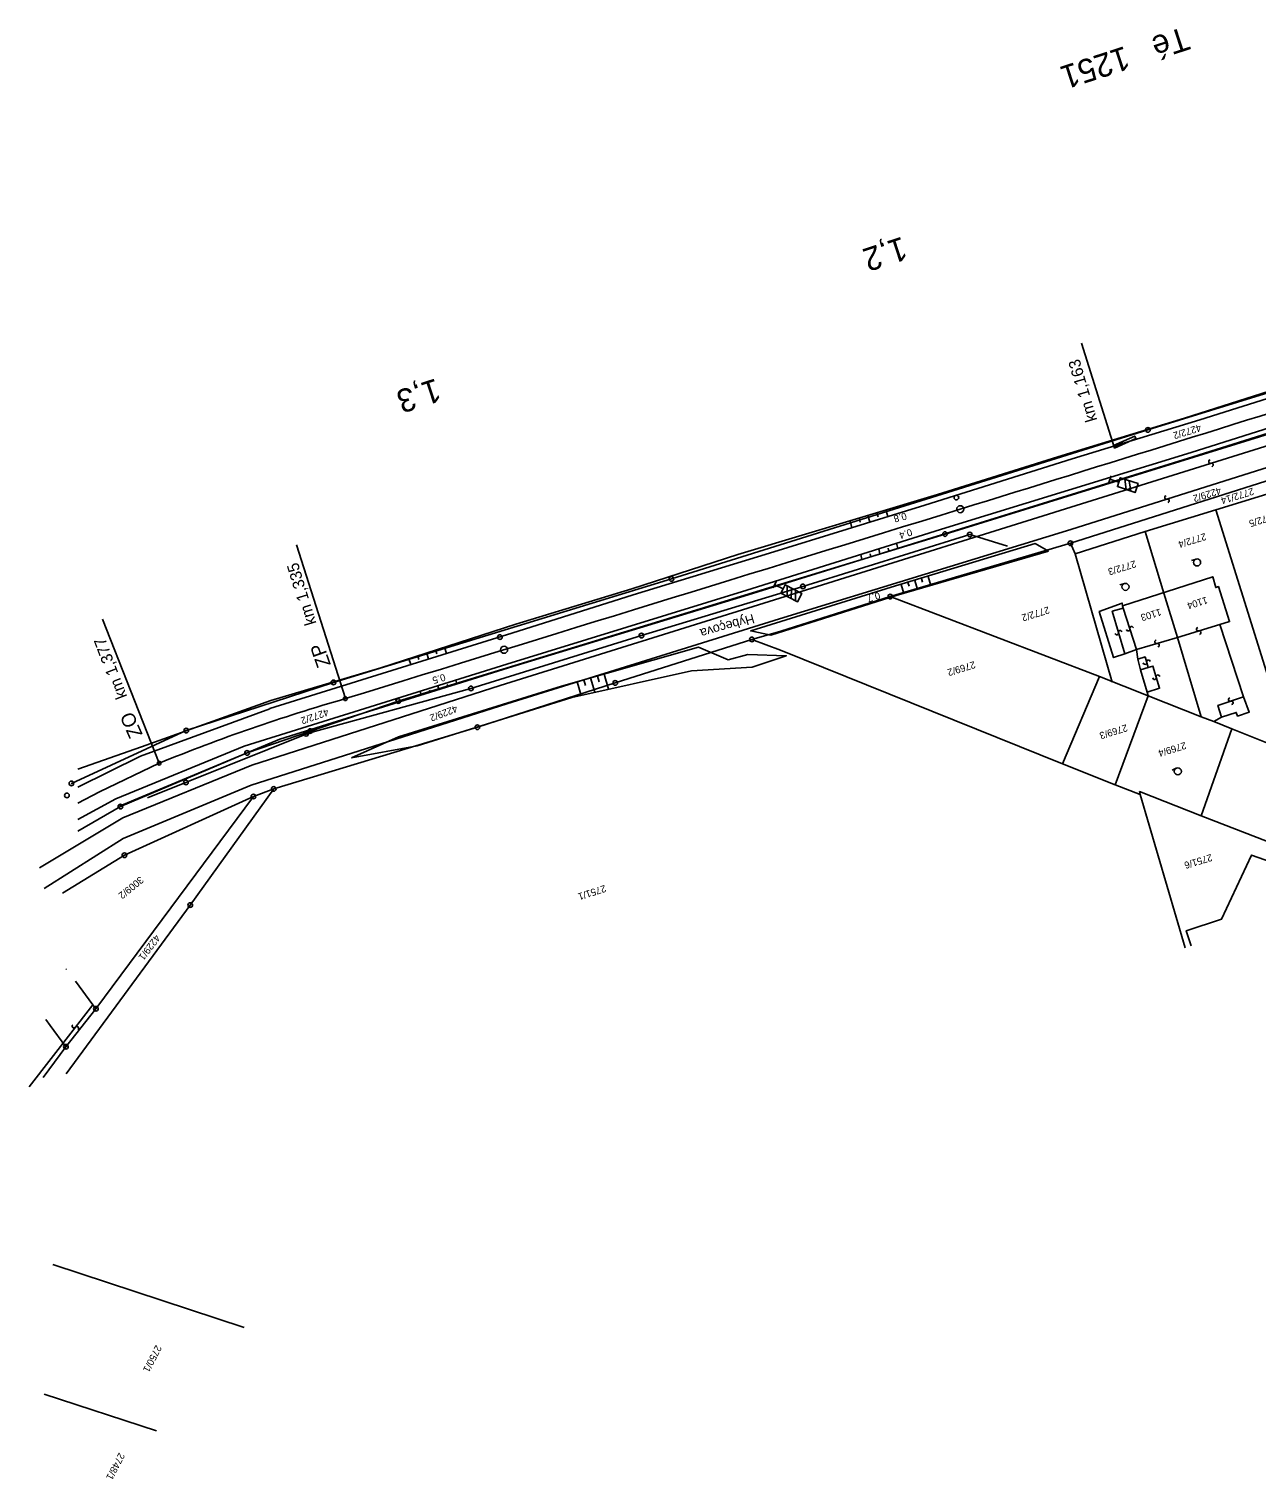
# Model space of a CAD drawing. Extents: x -658910 to -658078, y -1170373 to -1169331.
# Drawn here: x -658910.4 to -658648.2, y -1170242 to -1169932.4 of the extents above; entities that cross this region are included whole.
import ezdxf

# ---------------------------------------------------------------- set-up
doc = ezdxf.new("R2010")
doc.units = 0
for name, color, linetype in [('Vrstva 1', 7, 'Continuous'), ('Vrstva 10', 7, 'Continuous'), ('Vrstva 11', 7, 'Continuous'), ('Vrstva 14', 7, 'Continuous'), ('Vrstva 20', 7, 'Continuous'), ('Vrstva 26', 7, 'Continuous'), ('Vrstva 27', 7, 'Continuous'), ('Vrstva 38', 7, 'Continuous'), ('Vrstva 39', 7, 'Continuous'), ('Vrstva 6', 7, 'Continuous'), ('Vrstva 7', 7, 'Continuous'), ('Vrstva 8', 7, 'Continuous'), ('Vrstva 9', 7, 'Continuous')]:
    doc.layers.add(name, color=color, linetype=linetype)

msp = doc.modelspace()

# ---------------------------------------------------------------- linework, layer by layer
at = {"layer": 'Vrstva 1'}
for p, q in [((-658671.562, -1170017.973), (-658671.462, -1170017.973)), ((-658714.89, -1170040.211), (-658714.79, -1170040.211)), ((-658773.316, -1170049.791), (-658773.216, -1170049.791)), ((-658845.488, -1170071.906), (-658845.388, -1170071.906)), ((-658831.616, -1170075.877), (-658831.516, -1170075.877)), ((-658876.886, -1170082.189), (-658876.786, -1170082.189)), ((-658863.921, -1170086.955), (-658863.821, -1170086.955)), ((-658901.421, -1170093.457), (-658901.321, -1170093.457)), ((-658890.964, -1170098.41), (-658890.864, -1170098.41))]:
    msp.add_line(p, q, dxfattribs=at)
for points in [[(-658750.043, -1170042.514), (-658671.512, -1170017.973), (-658613.207, -1169999.979)], [(-658585.293, -1169999.957), (-658599.563, -1170004.705), (-658613.664, -1170008.939), (-658714.84, -1170040.211), (-658749.914, -1170050.912)], [(-658901.371, -1170093.457), (-658901.371, -1170093.457), (-658876.836, -1170082.189), (-658845.438, -1170071.906), (-658773.266, -1170049.791), (-658750.043, -1170042.514)], [(-658900.009, -1170103.697), (-658890.914, -1170098.41), (-658863.871, -1170086.955), (-658831.566, -1170075.877), (-658749.914, -1170050.912)]]:
    msp.add_lwpolyline(points, dxfattribs=at)
for centre in [(-658671.512, -1170017.973), (-658714.84, -1170040.211), (-658773.266, -1170049.791), (-658845.438, -1170071.906), (-658831.566, -1170075.877), (-658876.836, -1170082.189), (-658863.871, -1170086.955), (-658901.371, -1170093.457), (-658890.914, -1170098.41)]:
    msp.add_circle(centre, 0.499, dxfattribs=at)
at = {"layer": 'Vrstva 10'}
for p, q in [((-658735.117, -1170037.368), (-658734.704, -1170038.861)), ((-658733.201, -1170036.793), (-658732.958, -1170037.672)), ((-658731.286, -1170036.218), (-658730.881, -1170037.682)), ((-658729.37, -1170035.644), (-658729.127, -1170036.522)), ((-658727.455, -1170035.069), (-658727.058, -1170036.504)), ((-658728.759, -1170044.471), (-658728.984, -1170043.394)), ((-658726.849, -1170043.877), (-658726.984, -1170043.231)), ((-658724.939, -1170043.284), (-658725.166, -1170042.2)), ((-658732.579, -1170045.657), (-658732.803, -1170044.587)), ((-658730.669, -1170045.064), (-658730.804, -1170044.418)), ((-658825.509, -1170065.628), (-658825.088, -1170066.909)), ((-658823.607, -1170065.01), (-658823.354, -1170065.779)), ((-658821.704, -1170064.393), (-658821.269, -1170065.719)), ((-658829.314, -1170066.862), (-658828.907, -1170068.099)), ((-658827.412, -1170066.245), (-658827.159, -1170067.013)), ((-658819.071, -1170072.253), (-658819.277, -1170071.413)), ((-658826.709, -1170074.635), (-658826.913, -1170073.8)), ((-658824.799, -1170074.039), (-658824.922, -1170073.537)), ((-658822.89, -1170073.444), (-658823.095, -1170072.607)), ((-658820.981, -1170072.849), (-658821.104, -1170072.346))]:
    msp.add_line(p, q, dxfattribs=at)
for points in [[(-658858.81, -1170075.77), (-658835.33, -1170068.814), (-658806.5, -1170059.46), (-658781.728, -1170051.951), (-658759.08, -1170044.56), (-658716.43, -1170031.76), (-658690.72, -1170023.742), (-658663.72, -1170015.47), (-658630.927, -1170005.047), (-658619.527, -1170001.735), (-658614.09, -1169999.864), (-658613.911, -1169996.427), (-658615.839, -1169976.036), (-658616.28, -1169953.162), (-658614.25, -1169933.651)], [(-658610.105, -1169934.508), (-658612.959, -1169952.166), (-658613.171, -1169975.75), (-658611.485, -1169997.195), (-658611.739, -1169999.997), (-658613.983, -1170001.632), (-658619.297, -1170002.886), (-658632.661, -1170007.108), (-658660.45, -1170015.82), (-658687.716, -1170024.188), (-658719.16, -1170034.07), (-658752.32, -1170044.29), (-658781.421, -1170053.208), (-658807.34, -1170061.38), (-658834.998, -1170069.996)], [(-658623.66, -1170011.73), (-658661.96, -1170023.72), (-658756.86, -1170053.2), (-658808.03, -1170068.81), (-658856.9, -1170084.05), (-658891.09, -1170098.33)], [(-658714.67, -1170038.92), (-658662.28, -1170022.82), (-658628.54, -1170012.15)], [(-658900, -1170101.182), (-658891.86, -1170096.79), (-658864.47, -1170085.54), (-658808.39, -1170068.01), (-658757.16, -1170052.2), (-658714.67, -1170038.92)], [(-658721.308, -1170050.141), (-658720.723, -1170052.062)], [(-658719.873, -1170049.704), (-658719.637, -1170050.48)], [(-658718.438, -1170049.267), (-658717.841, -1170051.227)], [(-658724.178, -1170051.016), (-658723.604, -1170052.896)], [(-658722.743, -1170050.579), (-658722.511, -1170051.338)], [(-658834.998, -1170069.996), (-658859.033, -1170077.493)], [(-658793.385, -1170071.78), (-658792.557, -1170074.672)], [(-658791.942, -1170071.368), (-658791.602, -1170072.559)], [(-658790.5, -1170070.955), (-658789.624, -1170074.018)], [(-658789.058, -1170070.542), (-658788.698, -1170071.802)], [(-658787.616, -1170070.13), (-658786.691, -1170073.365)], [(-658858.81, -1170075.77), (-658886.37, -1170085.64), (-658900, -1170090.433)], [(-658900, -1170094.262), (-658886.64, -1170087.67), (-658858.98, -1170077.52)]]:
    msp.add_lwpolyline(points, dxfattribs=at)
for points in [[(-658692.759, -1170043.892), (-658695.624, -1170042.243), (-658726.306, -1170051.594), (-658756.332, -1170060.903), (-658752.062, -1170061.801), (-658725.258, -1170053.308)], [(-658841.563, -1170088.023), (-658831.521, -1170083.504), (-658796.721, -1170072.734), (-658767.485, -1170064.372), (-658761.109, -1170067.059), (-658756.94, -1170065.949), (-658748.723, -1170066.215), (-658755.985, -1170068.673), (-658768.941, -1170069.411), (-658794.544, -1170075.114), (-658827.528, -1170085.418)]]:
    msp.add_lwpolyline(points, close=True, dxfattribs=at)
at = {"layer": 'Vrstva 14'}
for centre in [(-658712.42, -1170032.43), (-658809.87, -1170062.23), (-658902.32, -1170096.04)]:
    msp.add_circle(centre, 0.5, dxfattribs=at)
at = {"layer": 'Vrstva 20'}
for p, q in [((-658679.383, -1170027.798), (-658679.857, -1170029.222)), ((-658676.458, -1170028.51), (-658676.141, -1170030.724)), ((-658675.193, -1170031.04), (-658675.509, -1170028.826)), ((-658750.867, -1170050.362), (-658751.553, -1170051.698)), ((-658748.529, -1170051.283), (-658748.554, -1170053.518)), ((-658747.664, -1170053.976), (-658747.639, -1170051.74)), ((-658746.751, -1170052.196), (-658746.774, -1170054.433))]:
    msp.add_line(p, q, dxfattribs=at)
for points in [[(-658679.62, -1170028.51), (-658677.723, -1170029.142), (-658678.039, -1170030.091), (-658674.244, -1170031.356), (-658673.612, -1170029.459), (-658677.406, -1170028.194), (-658677.723, -1170029.142)], [(-658751.21, -1170051.03), (-658749.431, -1170051.943), (-658749.888, -1170052.833), (-658746.33, -1170054.661), (-658745.416, -1170052.882), (-658748.974, -1170051.055), (-658749.431, -1170051.943)]]:
    msp.add_lwpolyline(points, dxfattribs=at)
at = {"layer": 'Vrstva 26'}
for p, q in [((-658678.468, -1170021.115), (-658678.706, -1170021.723)), ((-658677.982, -1170020.903), (-658678.291, -1170021.693)), ((-658677.496, -1170020.69), (-658677.805, -1170021.48)), ((-658677.038, -1170020.546), (-658677.32, -1170021.267)), ((-658676.818, -1170021.048), (-658677.059, -1170020.498)), ((-658676.824, -1170021.032), (-658676.833, -1170021.055)), ((-658676.818, -1170021.048), (-658676.818, -1170021.048))]:
    msp.add_line(p, q, dxfattribs=at)
for points in [[(-658674.069, -1170019.845), (-658678.65, -1170021.849), (-658678.891, -1170021.3), (-658674.311, -1170019.295), (-658674.069, -1170019.845)], [(-658701.47, -1170042.819), (-658709.55, -1170040.34), (-658745.18, -1170051.4)], [(-658745.18, -1170051.4), (-658779.65, -1170061.91), (-658816.05, -1170073.17)], [(-658816.05, -1170073.17), (-658850.74, -1170082.75), (-658885.09, -1170096.558)]]:
    msp.add_lwpolyline(points, dxfattribs=at)
msp.add_lwpolyline([(-658678.891, -1170021.3), (-658677.059, -1170020.498), (-658676.818, -1170021.048), (-658678.65, -1170021.849)], close=True, dxfattribs=at)
for centre in [(-658709.55, -1170040.34), (-658745.18, -1170051.4), (-658779.65, -1170061.91), (-658816.05, -1170073.17), (-658851.245, -1170082.857), (-658850.421, -1170082.287), (-658876.91, -1170093.27)]:
    msp.add_circle(centre, 0.5, dxfattribs=at)
at = {"layer": 'Vrstva 27'}
msp.add_line((-658678.65, -1170021.849), (-658685.668, -1169999.45), dxfattribs=at)
at = {"layer": 'Vrstva 38'}
for points in [[(-658853.304, -1170042.51), (-658842.88, -1170075.37)], [(-658894.763, -1170058.415), (-658882.62, -1170089.14)]]:
    msp.add_lwpolyline(points, dxfattribs=at)
for centre in [(-658842.88, -1170075.37), (-658882.62, -1170089.14)]:
    msp.add_circle(centre, 0.4, dxfattribs=at)
at = {"layer": 'Vrstva 6'}
msp.add_lwpolyline([(-658900, -1170097.715), (-658895.39, -1170095.24), (-658882.62, -1170089.14)], dxfattribs=at)
for centre in [(-658711.59, -1170034.91), (-658808.981, -1170064.933)]:
    msp.add_circle(centre, 0.75, dxfattribs=at)
for centre, radius, start, end in [((-665545.791, -1147911.264), 23155.173, 287.1664083, 287.4078056), ((-547459.91, -1531272.432), 377980.798, 107.11745833, 107.13828333), ((-658732.91, -1170456.97), 397.13, 106.07594, 112.14669)]:
    msp.add_arc(centre, radius, start, end, dxfattribs=at)
at = {"layer": 'Vrstva 8'}
for p, q in [((-658688.128, -1170042.182), (-658688.028, -1170042.182)), ((-658688.128, -1170042.182), (-658688.028, -1170042.182)), ((-658726.577, -1170053.572), (-658726.477, -1170053.572)), ((-658726.577, -1170053.572), (-658726.477, -1170053.572)), ((-658756.113, -1170062.727), (-658756.013, -1170062.727)), ((-658756.113, -1170062.727), (-658756.013, -1170062.727)), ((-658785.304, -1170072.021), (-658785.204, -1170072.021)), ((-658814.745, -1170081.465), (-658814.645, -1170081.465)), ((-658862.542, -1170096.26), (-658862.442, -1170096.26)), ((-658862.542, -1170096.26), (-658862.442, -1170096.26)), ((-658858.23, -1170094.633), (-658858.13, -1170094.633)), ((-658858.23, -1170094.633), (-658858.13, -1170094.633)), ((-658890.089, -1170108.813), (-658889.989, -1170108.813)), ((-658876.038, -1170119.434), (-658875.938, -1170119.434)), ((-658896.195, -1170141.572), (-658896.095, -1170141.572)), ((-658896.195, -1170141.572), (-658896.095, -1170141.572)), ((-658902.581, -1170149.688), (-658902.481, -1170149.688)), ((-658902.581, -1170149.688), (-658902.481, -1170149.688))]:
    msp.add_line(p, q, dxfattribs=at)
for points in [[(-658750.074, -1170053.912), (-658680.031, -1170031.988), (-658636.086, -1170018.248), (-658589.152, -1170004.176), (-658575.438, -1170000.053)], [(-658750.188, -1170058.359), (-658687.98, -1170039.244), (-658646.949, -1170026.285), (-658597.125, -1170011.18), (-658596.484, -1170013.23), (-658607.781, -1170016.664), (-658688.078, -1170042.182), (-658726.527, -1170053.572), (-658749.891, -1170060.961)], [(-658640.809, -1170086.922), (-658656.988, -1170035.021), (-658641.512, -1170030.291), (-658637.563, -1170043.293), (-658635.52, -1170050.398), (-658634.996, -1170051.859), (-658633.07, -1170058.375), (-658626.898, -1170077.652), (-658633.539, -1170089.834)], [(-658656.988, -1170035.021), (-658672.113, -1170039.701)], [(-658687.063, -1170044.438), (-658672.113, -1170039.701), (-658668.121, -1170052.848), (-658665.195, -1170062.299), (-658660.113, -1170079.238)], [(-658679.133, -1170071.836), (-658687.063, -1170044.438), (-658688.078, -1170042.182)], [(-658651.086, -1170074.998), (-658656.168, -1170059.514), (-658654.09, -1170058.92), (-658656.449, -1170051.438), (-658657.016, -1170051.652), (-658657.68, -1170049.348), (-658676.922, -1170055.516), (-658676.77, -1170056.045), (-658673.926, -1170064.844), (-658673.699, -1170066.908), (-658672.105, -1170066.453), (-658671.457, -1170068.709), (-658670.441, -1170068.42), (-658669.027, -1170073.158), (-658671.672, -1170073.965), (-658673.094, -1170069.205), (-658671.457, -1170068.709)], [(-658908.199, -1170111.508), (-658890.367, -1170100.813), (-658862.824, -1170089.561), (-658809.809, -1170072.594), (-658750.074, -1170053.912)], [(-658681.879, -1170070.646), (-658726.527, -1170053.572)], [(-658656.168, -1170059.514), (-658665.195, -1170062.299), (-658673.926, -1170064.844), (-658676.469, -1170065.828), (-658678.855, -1170066.613), (-658681.895, -1170056.779), (-658676.98, -1170054.961), (-658676.922, -1170055.516)], [(-658676.77, -1170056.045), (-658679.141, -1170056.721), (-658676.469, -1170065.828)], [(-658750.188, -1170058.359), (-658808.418, -1170076.5), (-658844.629, -1170088.006), (-658862.988, -1170093.809), (-658890.281, -1170105.262), (-658907.157, -1170115.934)], [(-658749.891, -1170060.961), (-658756.063, -1170062.727)], [(-658902.517, -1170155.47), (-658875.988, -1170119.434), (-658858.18, -1170094.633), (-658814.695, -1170081.465), (-658785.254, -1170072.021), (-658756.063, -1170062.727), (-658749.953, -1170065.01)], [(-658749.953, -1170065.01), (-658689.758, -1170089.258), (-658678.52, -1170093.789), (-658673.168, -1170095.848), (-658663.594, -1170128.594)], [(-658673.094, -1170069.205), (-658673.699, -1170066.908)], [(-658689.758, -1170089.258), (-658681.879, -1170070.646), (-658671.484, -1170074.795), (-658678.52, -1170093.789)], [(-658671.672, -1170073.965), (-658671.484, -1170074.795)], [(-658671.484, -1170074.795), (-658660.113, -1170079.238), (-658657.473, -1170080.25), (-658653.578, -1170081.787), (-658640.809, -1170086.922), (-658633.539, -1170089.834), (-658623.715, -1170093.627), (-658608.461, -1170099.402), (-658611.504, -1170107.906)], [(-658657.473, -1170080.25), (-658655.793, -1170079.355), (-658652.645, -1170078.301), (-658652.363, -1170079.104), (-658649.879, -1170078.289), (-658651.086, -1170074.998), (-658656.574, -1170076.824), (-658655.793, -1170079.355)], [(-658660.148, -1170100.391), (-658653.578, -1170081.787)], [(-658862.492, -1170096.26), (-658896.145, -1170141.572), (-658902.531, -1170149.688), (-658907.404, -1170156.249)], [(-658903.276, -1170116.909), (-658890.039, -1170108.813), (-658862.492, -1170096.26), (-658858.18, -1170094.633)], [(-658626.145, -1170113.541), (-658660.148, -1170100.391), (-658673.301, -1170095.209), (-658673.168, -1170095.848)], [(-658662.316, -1170128.127), (-658663.34, -1170124.938), (-658655.801, -1170122.422), (-658649.43, -1170108.76), (-658630.473, -1170115.4)], [(-658902.383, -1170133.092), (-658902.535, -1170133.202)], [(-658900.498, -1170135.681), (-658896.793, -1170140.77), (-658896.145, -1170141.572)], [(-658896.793, -1170140.77), (-658910.422, -1170158.293)], [(-658902.531, -1170149.688), (-658905.875, -1170145.17), (-658906.838, -1170143.909)], [(-658905.369, -1170196.205), (-658864.461, -1170209.621)], [(-658907.19, -1170223.865), (-658883.211, -1170231.717)]]:
    msp.add_lwpolyline(points, dxfattribs=at)
for centre in [(-658688.078, -1170042.182), (-658688.078, -1170042.182), (-658726.527, -1170053.572), (-658726.527, -1170053.572), (-658756.063, -1170062.727), (-658756.063, -1170062.727), (-658785.254, -1170072.021), (-658814.695, -1170081.465), (-658862.492, -1170096.26), (-658862.492, -1170096.26), (-658858.18, -1170094.633), (-658858.18, -1170094.633), (-658890.039, -1170108.813), (-658875.988, -1170119.434), (-658896.145, -1170141.572), (-658896.145, -1170141.572), (-658902.531, -1170149.688), (-658902.531, -1170149.688)]:
    msp.add_circle(centre, 0.499, dxfattribs=at)
for centre, radius, start, end in [((-658658.167, -1170024.756), 0.376, 100.39308, 286.70422), ((-658657.946, -1170025.476), 0.377, 279.71704, 107.38026), ((-658667.574, -1170032.403), 0.376, 100.55814, 286.86928), ((-658667.351, -1170033.123), 0.377, 279.8821, 107.54532), ((-658678.167, -1170061.374), 0.376, 189.38066, 15.6918), ((-658677.443, -1170061.166), 0.377, 8.70462, 196.36784), ((-658675.707, -1170060.554), 0.376, 190.941, 17.25213), ((-658674.989, -1170060.327), 0.377, 10.26496, 197.92817), ((-658660.786, -1170060.545), 0.376, 100.17663, 286.48776), ((-658660.568, -1170061.265), 0.377, 279.50059, 107.1638), ((-658669.664, -1170063.209), 0.376, 99.28171, 285.59284), ((-658669.457, -1170063.933), 0.377, 278.60566, 106.26888), ((-658672.143, -1170067.679), 0.376, 189.06743, 15.37856), ((-658671.418, -1170067.475), 0.377, 8.39139, 196.0546), ((-658670.095, -1170070.892), 0.376, 189.64721, 15.95834), ((-658669.373, -1170070.681), 0.377, 8.97116, 196.63438), ((-658653.942, -1170075.551), 0.376, 101.43472, 287.74585), ((-658653.709, -1170076.267), 0.377, 280.75868, 108.42189), ((-658900.831, -1170145.286), 0.376, 134.79213, 321.10327), ((-658900.243, -1170145.756), 0.377, 314.11609, 141.77931)]:
    msp.add_arc(centre, radius, start, end, dxfattribs=at)
at = {"layer": 'Vrstva 9'}
for p, q in [((-658661.234, -1170045.566), (-658662.19, -1170045.858)), ((-658676.523, -1170050.777), (-658677.479, -1170051.069)), ((-658665.453, -1170090.217), (-658666.354, -1170090.65))]:
    msp.add_line(p, q, dxfattribs=at)
for centre in [(-658661.014, -1170046.283), (-658676.303, -1170051.494), (-658665.127, -1170090.892)]:
    msp.add_circle(centre, 0.75, dxfattribs=at)

# ---------------------------------------------------------------- texts
at = {"layer": 'Vrstva 11'}
for s, rotation, p in [('4272/2', 197.15141, (-658660.403, -1170016.754)), ('0.8', 195.46354, (-658723.256, -1170035.605)), ('0.4', 197.72474, (-658722.131, -1170039.043)), ('0,7', 196.95334, (-658728.945, -1170052.565)), ('0.5', 196.49234, (-658821.761, -1170070.031)), ('4272/2', 198.92819, (-658846.735, -1170077.48))]:
    msp.add_text(s, height=1.5, rotation=rotation, dxfattribs=at).set_placement(p)
at = {"layer": 'Vrstva 27'}
msp.add_text('km 1,163', height=2.5, rotation=106.21318, dxfattribs=at).set_placement((-658682.326, -1170015.878))
at = {"layer": 'Vrstva 39'}
for s, height, rotation, p in [('km 1,335', 2.5, 106.94394, (-658849.029, -1170059.28)), ('km 1,377', 2.5, 110.86654, (-658889.404, -1170074.903)), ('ZP', 3, 109.37219, (-658845.935, -1170068.104)), ('ZO', 3, 113.84422, (-658886.109, -1170083))]:
    msp.add_text(s, height=height, rotation=rotation, dxfattribs=at).set_placement(p)
at = {"layer": 'Vrstva 7'}
for s, p in [('Té   1251', (-658663.722, -1169931.841)), ('1,2', (-658723.948, -1169976.646)), ('1,3', (-658823.516, -1170006.907))]:
    msp.add_text(s, height=4.999, rotation=197.99256, dxfattribs=at).set_placement(p)
at = {"layer": 'Vrstva 9'}
for s, height, rotation, p in [('4229/2', 1.5, 197.15141, (-658656.152, -1170030.191)), ('2772/14', 1.5, 197.15141, (-658649.152, -1170030.318)), ('2772/5', 1.5, 197.15141, (-658644.211, -1170035.529)), ('2772/4', 1.5, 197.15141, (-658659.313, -1170039.977)), ('2772/3', 1.5, 197.15141, (-658674.301, -1170045.816)), ('2772/2', 1.5, 197.15141, (-658692.766, -1170055.658)), ('1103', 1.5, 197.15141, (-658668.922, -1170056.113)), ('1104', 1.5, 197.15141, (-658659.035, -1170053.572)), ('Hybeçova', 2, 196.00954, (-658755.878, -1170057.273)), ('2769/2', 1.5, 197.15141, (-658708.613, -1170067.336)), ('4229/2', 1.5, 200.67094, (-658819.254, -1170076.72)), ('2769/3', 1.5, 197.15141, (-658676.133, -1170080.826)), ('2769/4', 1.5, 197.15141, (-658663.586, -1170084.588)), ('2751/6', 1.5, 197.15141, (-658658.039, -1170108.51)), ('3009/2', 1.5, 219.09355, (-658886.703, -1170113.228)), ('2751/1', 1.5, 197.78369, (-658787.496, -1170115.131)), ('4229/1', 1.5, 233.02161, (-658883.449, -1170125.619)), ('2750/1', 1.5, 242.67212, (-658883.325, -1170213.257)), ('2748/1', 1.5, 242.67212, (-658891.189, -1170236.245))]:
    msp.add_text(s, height=height, rotation=rotation, dxfattribs=at).set_placement(p)

doc.saveas('drawing.dxf')
